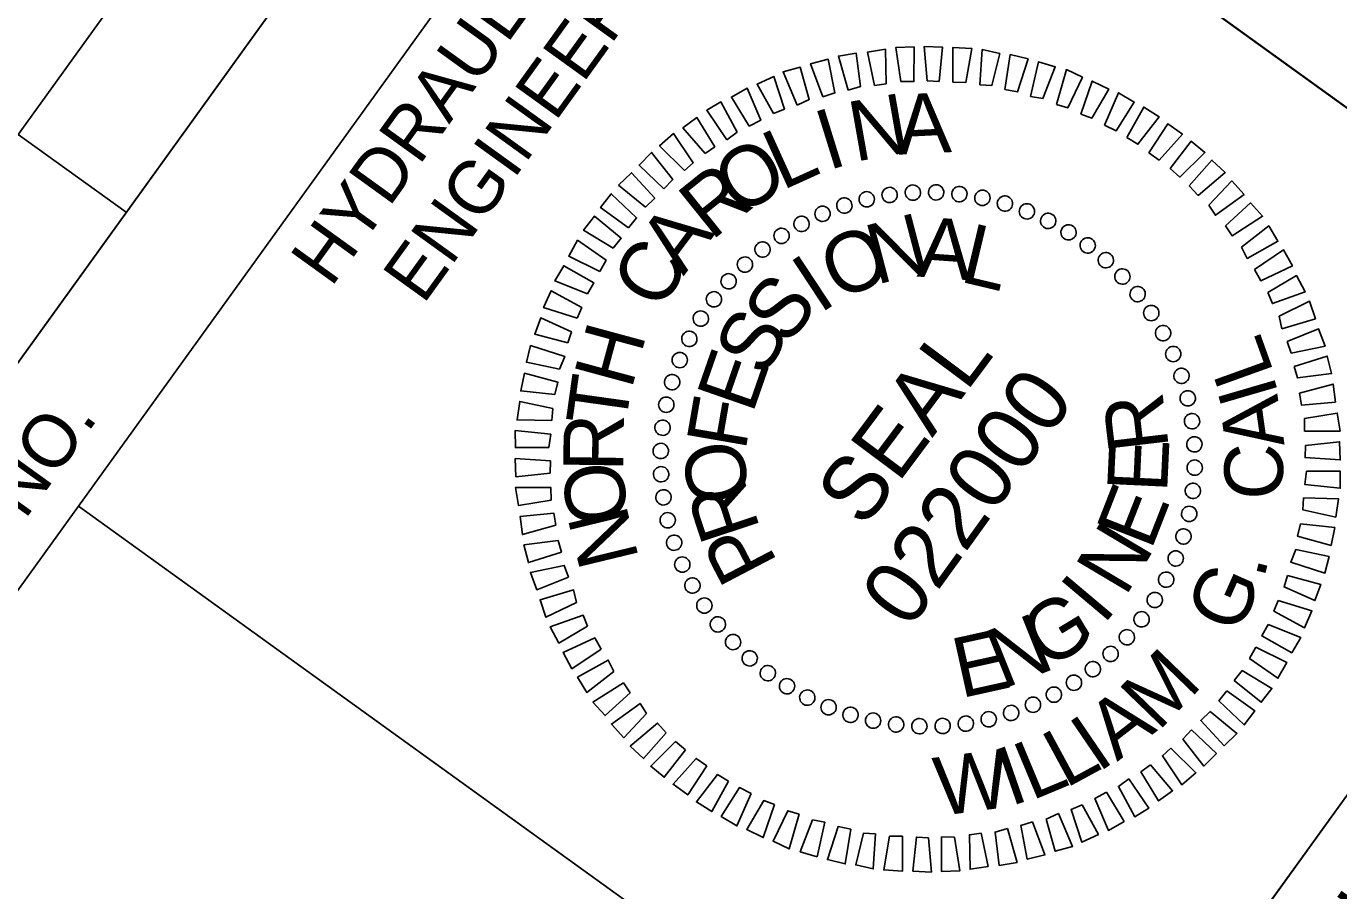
# Model space of a CAD drawing. Extents: x 2186840 to 2191350, y 386817 to 390793.
# Drawn here: x 2190437.4 to 2190560.6, y 388656.7 to 388737.9 of the extents above; entities that cross this region are included whole.
import ezdxf

# ---------------------------------------------------------------- set-up
doc = ezdxf.new("R2010")
doc.units = 0
for name, color, linetype in [('Sheet Plan CELL', 7, 'Continuous'), ('Sheet Plan Layout CELL', 7, 'Continuous'), ('Sheet Professional Seal CELL', 7, 'Continuous'), ('Sheet Sticker Exception Certification CELL', 7, 'Continuous')]:
    doc.layers.add(name, color=color, linetype=linetype)

msp = doc.modelspace()

# ---------------------------------------------------------------- linework, layer by layer
at = {"layer": 'Sheet Plan CELL'}
for p, q in [((2190363.46, 388626.27), (2190480.48, 388788.52)), ((2190373.63, 388618.95), (2190490.62, 388781.21)), ((2190373.63, 388618.95), (2190490.62, 388781.21)), ((2190426.47, 388734.97), (2190446.77, 388720.39)), ((2190442.28, 388692.79), (2190533.51, 388627.02))]:
    msp.add_line(p, q, dxfattribs=at)
for points in [[(2190470.32, 388795.89), (2189592.9, 387579.24), (2190444.54, 386965.06), (2191321.95, 388181.69)], [(2190353.28, 388633.62), (2190470.32, 388795.89), (2190490.62, 388781.21), (2190373.63, 388618.95)], [(2190442.28, 388692.79), (2190500.76, 388773.9), (2190592.02, 388708.09), (2190533.54, 388626.98)], [(2190444.54, 386965.06), (2189592.91, 387579.2), (2190353.28, 388633.62), (2190475, 388545.85), (2190592.02, 388708.09), (2191321.95, 388181.69)], [(2190383.76, 388611.64), (2190442.28, 388692.79), (2190533.54, 388626.98), (2190475, 388545.85)]]:
    msp.add_lwpolyline(points, close=True, dxfattribs=at)
at = {"layer": 'Sheet Plan Layout CELL'}
msp.add_lwpolyline([(2190501.89, 388478.1), (2190641.85, 388672.18), (2190470.33, 388795.9), (2190330.36, 388601.81)], close=True, dxfattribs=at)
at = {"layer": 'Sheet Professional Seal CELL'}
for p, q in [((2190516.31, 388721.65), (2190516.31, 388721.65)), ((2190518.44, 388722.03), (2190518.44, 388722.03)), ((2190520.65, 388722.28), (2190520.65, 388722.28)), ((2190522.8, 388722.27), (2190522.8, 388722.27)), ((2190525.02, 388722.1), (2190525.02, 388722.1)), ((2190527.18, 388721.77), (2190527.18, 388721.77)), ((2190514.19, 388721.02), (2190514.19, 388721.02)), ((2190529.27, 388721.25), (2190529.27, 388721.25)), ((2190531.33, 388720.5), (2190531.33, 388720.5)), ((2190510.18, 388719.3), (2190510.18, 388719.3)), ((2190512.13, 388720.29), (2190512.13, 388720.29)), ((2190533.34, 388719.54), (2190533.34, 388719.54)), ((2190508.28, 388718.2), (2190508.28, 388718.2)), ((2190535.26, 388718.53), (2190535.26, 388718.53)), ((2190506.48, 388716.91), (2190506.48, 388716.91)), ((2190537.08, 388717.28), (2190537.08, 388717.28)), ((2190504.89, 388715.47), (2190504.89, 388715.47)), ((2190538.77, 388715.87), (2190538.77, 388715.87)), ((2190540.31, 388714.33), (2190540.31, 388714.33)), ((2190503.34, 388713.93), (2190503.34, 388713.93)), ((2190501.94, 388712.23), (2190501.94, 388712.23)), ((2190541.75, 388712.74), (2190541.75, 388712.74)), ((2190543.05, 388710.94), (2190543.05, 388710.94)), ((2190500.69, 388710.42), (2190500.69, 388710.42)), ((2190499.68, 388708.5), (2190499.68, 388708.5)), ((2190544.14, 388709.04), (2190544.14, 388709.04)), ((2190545.14, 388707.09), (2190545.14, 388707.09)), ((2190498.71, 388706.48), (2190498.71, 388706.48)), ((2190497.97, 388704.43), (2190497.97, 388704.43)), ((2190545.87, 388705.02), (2190545.87, 388705.02)), ((2190497.45, 388702.34), (2190497.45, 388702.34)), ((2190546.5, 388702.9), (2190546.5, 388702.9)), ((2190546.88, 388700.78), (2190546.88, 388700.78)), ((2190497.12, 388700.17), (2190497.12, 388700.17)), ((2190547.13, 388698.57), (2190547.13, 388698.57)), ((2190496.94, 388697.96), (2190496.94, 388697.96)), ((2190522.03, 388697.19), (2190522.03, 388697.19)), ((2190496.93, 388695.81), (2190496.93, 388695.81)), ((2190547.12, 388696.41), (2190547.12, 388696.41)), ((2190497.18, 388693.59), (2190497.18, 388693.59)), ((2190546.94, 388694.2), (2190546.94, 388694.2)), ((2190546.61, 388692.03), (2190546.61, 388692.03)), ((2190497.56, 388691.47), (2190497.56, 388691.47)), ((2190546.09, 388689.94), (2190546.09, 388689.94)), ((2190498.19, 388689.35), (2190498.19, 388689.35)), ((2190498.92, 388687.28), (2190498.92, 388687.28)), ((2190545.35, 388687.89), (2190545.35, 388687.89)), ((2190544.39, 388685.87), (2190544.39, 388685.87)), ((2190499.92, 388685.33), (2190499.92, 388685.33)), ((2190501.01, 388683.43), (2190501.01, 388683.43)), ((2190543.37, 388683.95), (2190543.37, 388683.95)), ((2190502.31, 388681.63), (2190502.31, 388681.63)), ((2190542.13, 388682.14), (2190542.13, 388682.14)), ((2190503.75, 388680.04), (2190503.75, 388680.04)), ((2190540.72, 388680.44), (2190540.72, 388680.44)), ((2190505.29, 388678.5), (2190505.29, 388678.5)), ((2190539.18, 388678.9), (2190539.18, 388678.9)), ((2190537.58, 388677.46), (2190537.58, 388677.46)), ((2190506.98, 388677.09), (2190506.98, 388677.09)), ((2190535.79, 388676.17), (2190535.79, 388676.17)), ((2190508.8, 388675.84), (2190508.8, 388675.84)), ((2190510.72, 388674.83), (2190510.72, 388674.83)), ((2190533.89, 388675.07), (2190533.89, 388675.07)), ((2190512.74, 388673.87), (2190512.74, 388673.87)), ((2190531.93, 388674.08), (2190531.93, 388674.08)), ((2190514.79, 388673.13), (2190514.79, 388673.13)), ((2190516.88, 388672.6), (2190516.88, 388672.6)), ((2190525.63, 388672.34), (2190525.63, 388672.34)), ((2190527.75, 388672.72), (2190527.75, 388672.72)), ((2190529.87, 388673.35), (2190529.87, 388673.35)), ((2190519.05, 388672.28), (2190519.05, 388672.28)), ((2190521.26, 388672.1), (2190521.26, 388672.1)), ((2190523.41, 388672.09), (2190523.41, 388672.09))]:
    msp.add_line(p, q, dxfattribs=at)
for points in [[(2190514.55, 388731.86), (2190513.64, 388735.05), (2190515.32, 388735.32), (2190515.71, 388732.19)], [(2190517.02, 388732.3), (2190516.37, 388735.42), (2190518.05, 388735.69), (2190518.11, 388732.44)], [(2190519.51, 388732.66), (2190519.03, 388735.85), (2190520.74, 388735.91), (2190520.73, 388732.65)], [(2190521.97, 388732.74), (2190521.7, 388735.96), (2190523.43, 388735.88), (2190523.09, 388732.67)], [(2190524.39, 388732.6), (2190524.4, 388735.86), (2190526.17, 388735.75), (2190525.61, 388732.58)], [(2190526.93, 388732.36), (2190527.15, 388735.66), (2190528.79, 388735.28), (2190528.06, 388732.29)], [(2190529.26, 388731.92), (2190529.77, 388735.19), (2190531.45, 388734.78), (2190530.45, 388731.68)], [(2190509.77, 388730.44), (2190508.44, 388733.56), (2190510.05, 388734), (2190510.9, 388730.98)], [(2190512.18, 388731.23), (2190511.03, 388734.34), (2190512.69, 388734.75), (2190513.31, 388731.59)], [(2190531.69, 388731.27), (2190532.42, 388734.51), (2190534, 388734.05), (2190532.84, 388731.06)], [(2190507.53, 388729.65), (2190506.01, 388732.41), (2190507.58, 388733.13), (2190508.57, 388730.07)], [(2190534.11, 388730.52), (2190535.05, 388733.79), (2190536.56, 388733.06), (2190535.17, 388730.19)], [(2190536.41, 388729.6), (2190537.48, 388732.71), (2190539.03, 388731.96), (2190537.43, 388729.23)], [(2190505.25, 388728.46), (2190503.59, 388731.2), (2190505.07, 388732.04), (2190506.34, 388729.03)], [(2190538.62, 388728.56), (2190539.95, 388731.61), (2190541.42, 388730.73), (2190539.71, 388728.02)], [(2190503.17, 388727.19), (2190501.28, 388729.96), (2190502.59, 388730.75), (2190504.12, 388727.92)], [(2190540.74, 388727.4), (2190542.32, 388730.27), (2190543.75, 388729.36), (2190541.77, 388726.78)], [(2190501.12, 388725.89), (2190499.04, 388728.31), (2190500.36, 388729.28), (2190502.02, 388726.54)], [(2190542.8, 388725.98), (2190544.58, 388728.7), (2190545.95, 388727.71), (2190543.77, 388725.28)], [(2190499.19, 388724.32), (2190496.85, 388726.63), (2190498.16, 388727.77), (2190500.01, 388725.03)], [(2190544.79, 388724.48), (2190546.78, 388727.05), (2190548.06, 388726.01), (2190545.71, 388723.69)], [(2190497.25, 388722.58), (2190494.92, 388724.81), (2190496.09, 388726.01), (2190498.08, 388723.46)], [(2190495.52, 388720.86), (2190493, 388722.93), (2190494.21, 388724.09), (2190496.39, 388721.72)], [(2190546.59, 388722.87), (2190548.71, 388725.29), (2190549.97, 388724.13), (2190547.42, 388721.96)], [(2190548.43, 388721.05), (2190550.57, 388723.33), (2190551.74, 388722.06), (2190549.05, 388720.11)], [(2190493.94, 388718.92), (2190491.3, 388720.82), (2190492.31, 388722.13), (2190494.68, 388719.87)], [(2190550, 388719.12), (2190552.34, 388721.26), (2190553.47, 388720.01), (2190550.61, 388718.18)], [(2190492.49, 388717.01), (2190489.71, 388718.7), (2190490.72, 388720.01), (2190493.24, 388717.95)], [(2190551.5, 388717.11), (2190554.05, 388719.1), (2190554.92, 388717.66), (2190552.03, 388716.05)], [(2190491.24, 388714.83), (2190488.32, 388716.26), (2190489.15, 388717.75), (2190491.82, 388715.89)], [(2190552.7, 388715.01), (2190555.45, 388716.85), (2190556.27, 388715.34), (2190553.3, 388713.96)], [(2190490.07, 388712.71), (2190487.01, 388713.93), (2190487.85, 388715.36), (2190490.66, 388713.77)], [(2190553.98, 388712.86), (2190556.66, 388714.44), (2190557.48, 388712.92), (2190554.4, 388711.81)], [(2190489.12, 388710.44), (2190485.95, 388711.43), (2190486.66, 388713.02), (2190489.53, 388711.44)], [(2190555.03, 388710.62), (2190557.88, 388712.02), (2190558.43, 388710.39), (2190555.29, 388709.45)], [(2190488.24, 388708.12), (2190485.13, 388708.94), (2190485.68, 388710.46), (2190488.57, 388709.17)], [(2190555.77, 388708.24), (2190558.73, 388709.43), (2190559.35, 388707.82), (2190556.16, 388707.16)], [(2190487.46, 388705.66), (2190484.34, 388706.3), (2190484.73, 388707.87), (2190487.94, 388706.85)], [(2190556.43, 388705.91), (2190559.54, 388706.88), (2190559.95, 388705.23), (2190556.75, 388704.82)], [(2190487.02, 388703.26), (2190483.81, 388703.6), (2190484.15, 388705.27), (2190487.3, 388704.42)], [(2190556.95, 388703.38), (2190560.11, 388704.25), (2190560.31, 388702.56), (2190557.13, 388702.26)], [(2190486.74, 388700.82), (2190483.46, 388700.89), (2190483.72, 388702.62), (2190486.81, 388701.94)], [(2190557.41, 388701.02), (2190560.48, 388701.52), (2190560.75, 388699.84), (2190557.42, 388699.84)], [(2190486.46, 388698.3), (2190483.31, 388698.29), (2190483.3, 388699.9), (2190486.62, 388699.54)], [(2190557.49, 388698.49), (2190560.7, 388698.83), (2190560.76, 388697.12), (2190557.46, 388697.34)], [(2190486.57, 388695.88), (2190483.36, 388695.54), (2190483.3, 388697.25), (2190486.6, 388697.03)], [(2190557.6, 388696.07), (2190560.75, 388696.08), (2190560.76, 388694.47), (2190557.44, 388694.83)], [(2190486.66, 388693.35), (2190483.59, 388692.86), (2190483.31, 388694.53), (2190486.64, 388694.53)], [(2190557.32, 388693.56), (2190560.6, 388693.48), (2190560.34, 388691.75), (2190557.26, 388692.43)], [(2190487.11, 388690.99), (2190483.96, 388690.12), (2190483.75, 388691.81), (2190486.93, 388692.11)], [(2190557.04, 388691.11), (2190560.25, 388690.77), (2190559.91, 388689.1), (2190556.76, 388689.95)], [(2190487.63, 388688.46), (2190484.53, 388687.49), (2190484.11, 388689.14), (2190487.31, 388689.55)], [(2190556.61, 388688.71), (2190559.72, 388688.07), (2190559.33, 388686.5), (2190556.12, 388687.52)], [(2190488.29, 388686.13), (2190485.33, 388684.94), (2190484.71, 388686.56), (2190487.9, 388687.22)], [(2190555.82, 388686.26), (2190558.93, 388685.43), (2190558.39, 388683.91), (2190555.49, 388685.2)], [(2190489.04, 388683.75), (2190486.18, 388682.35), (2190485.63, 388683.98), (2190488.77, 388684.92)], [(2190554.94, 388683.93), (2190558.11, 388682.94), (2190557.4, 388681.35), (2190554.53, 388682.93)], [(2190490.08, 388681.52), (2190487.4, 388679.93), (2190486.58, 388681.45), (2190489.66, 388682.56)], [(2190553.99, 388681.66), (2190557.05, 388680.44), (2190556.21, 388679.01), (2190553.41, 388680.6)], [(2190491.36, 388679.36), (2190488.61, 388677.52), (2190487.79, 388679.03), (2190490.76, 388680.41)], [(2190552.83, 388679.54), (2190555.74, 388678.11), (2190554.91, 388676.62), (2190552.25, 388678.48)], [(2190492.56, 388677.26), (2190490.02, 388675.27), (2190489.14, 388676.71), (2190492.03, 388678.32)], [(2190551.57, 388677.36), (2190554.35, 388675.67), (2190553.34, 388674.36), (2190550.82, 388676.42)], [(2190494.07, 388675.25), (2190491.73, 388673.11), (2190490.59, 388674.36), (2190493.45, 388676.19)], [(2190550.12, 388675.45), (2190552.76, 388673.55), (2190551.75, 388672.24), (2190549.38, 388674.5)], [(2190495.63, 388673.32), (2190493.49, 388671.04), (2190492.32, 388672.32), (2190495.01, 388674.26)], [(2190497.47, 388671.5), (2190495.35, 388669.08), (2190494.09, 388670.24), (2190496.64, 388672.41)], [(2190548.54, 388673.51), (2190551.06, 388671.44), (2190549.85, 388670.28), (2190547.67, 388672.65)], [(2190546.81, 388671.79), (2190549.14, 388669.56), (2190547.97, 388668.37), (2190545.99, 388670.91)], [(2190499.27, 388669.89), (2190497.29, 388667.32), (2190496.01, 388668.36), (2190498.35, 388670.68)], [(2190544.87, 388670.05), (2190547.22, 388667.74), (2190545.9, 388666.6), (2190544.06, 388669.34)], [(2190501.27, 388668.39), (2190499.49, 388665.67), (2190498.11, 388666.66), (2190500.29, 388669.09)], [(2190503.32, 388666.97), (2190501.75, 388664.1), (2190500.31, 388665.01), (2190502.29, 388667.59)], [(2190542.94, 388668.48), (2190545.02, 388666.06), (2190543.7, 388665.1), (2190542.04, 388667.83)], [(2190505.44, 388665.81), (2190504.11, 388662.76), (2190502.64, 388663.64), (2190504.35, 388666.35)], [(2190540.9, 388667.18), (2190542.78, 388664.41), (2190541.47, 388663.62), (2190539.94, 388666.46)], [(2190507.65, 388664.77), (2190506.58, 388661.66), (2190505.03, 388662.41), (2190506.63, 388665.14)], [(2190538.81, 388665.91), (2190540.47, 388663.17), (2190539, 388662.33), (2190537.72, 388665.34)], [(2190509.95, 388663.85), (2190509.01, 388660.59), (2190507.5, 388661.31), (2190508.9, 388664.18)], [(2190534.3, 388663.93), (2190535.62, 388660.81), (2190534.01, 388660.37), (2190533.16, 388663.39)], [(2190536.53, 388664.72), (2190538.05, 388661.96), (2190536.49, 388661.24), (2190535.49, 388664.3)], [(2190512.37, 388663.1), (2190511.64, 388659.86), (2190510.06, 388660.33), (2190511.22, 388663.31)], [(2190514.8, 388662.45), (2190514.29, 388659.18), (2190512.61, 388659.59), (2190513.61, 388662.69)], [(2190529.51, 388662.51), (2190530.42, 388659.33), (2190528.75, 388659.05), (2190528.35, 388662.18)], [(2190531.88, 388663.14), (2190533.03, 388660.03), (2190531.38, 388659.62), (2190530.76, 388662.78)], [(2190517.13, 388662.01), (2190516.91, 388658.71), (2190515.27, 388659.09), (2190516.01, 388662.08)], [(2190519.67, 388661.78), (2190519.66, 388658.51), (2190517.89, 388658.62), (2190518.45, 388661.79)], [(2190522.1, 388661.63), (2190522.37, 388658.41), (2190520.63, 388658.49), (2190520.97, 388661.7)], [(2190524.55, 388661.71), (2190525.03, 388658.52), (2190523.33, 388658.46), (2190523.33, 388661.72)], [(2190527.04, 388662.07), (2190527.69, 388658.95), (2190526.01, 388658.68), (2190525.95, 388661.93)]]:
    msp.add_lwpolyline(points, close=True, dxfattribs=at)
for centre, major_axis in [((2190520.63, 388722.23), (-0.04, 0.719)), ((2190522.82, 388722.25), (0.023, 0.72)), ((2190525, 388722.09), (0.085, 0.715)), ((2190514.2, 388721.01), (-0.225, 0.684)), ((2190516.3, 388721.6), (-0.164, 0.701)), ((2190518.45, 388722.01), (-0.103, 0.713)), ((2190527.16, 388721.74), (0.147, 0.705)), ((2190529.28, 388721.2), (0.208, 0.689)), ((2190512.15, 388720.24), (-0.284, 0.662)), ((2190531.34, 388720.47), (0.267, 0.669)), ((2190533.34, 388719.57), (0.325, 0.643)), ((2190510.18, 388719.29), (-0.34, 0.635)), ((2190535.25, 388718.5), (0.379, 0.612)), ((2190508.3, 388718.17), (-0.394, 0.602)), ((2190537.05, 388717.27), (0.431, 0.577)), ((2190506.52, 388716.89), (-0.445, 0.566)), ((2190538.75, 388715.88), (0.48, 0.537)), ((2190504.86, 388715.47), (-0.493, 0.525)), ((2190503.33, 388713.9), (-0.537, 0.48)), ((2190540.31, 388714.35), (0.525, 0.493)), ((2190501.95, 388712.21), (-0.577, 0.431)), ((2190541.74, 388712.7), (0.566, 0.445)), ((2190500.72, 388710.4), (-0.612, 0.379)), ((2190543.02, 388710.92), (0.602, 0.394)), ((2190499.64, 388708.49), (-0.643, 0.325)), ((2190544.13, 388709.04), (0.635, 0.34)), ((2190498.74, 388706.5), (-0.669, 0.267)), ((2190545.08, 388707.07), (0.662, 0.284)), ((2190545.86, 388705.02), (0.684, 0.225)), ((2190498.02, 388704.43), (-0.689, 0.208)), ((2190546.45, 388702.91), (0.701, 0.164)), ((2190497.48, 388702.31), (-0.705, 0.147)), ((2190497.13, 388700.15), (-0.715, 0.085)), ((2190546.85, 388700.76), (0.713, 0.103)), ((2190496.96, 388697.97), (-0.72, 0.023)), ((2190547.07, 388698.59), (0.719, 0.04)), ((2190547.1, 388696.4), (0.72, -0.023)), ((2190496.99, 388695.78), (-0.719, -0.04)), ((2190546.93, 388694.22), (0.715, -0.085)), ((2190497.21, 388693.61), (-0.713, -0.103)), ((2190497.61, 388691.46), (-0.701, -0.164)), ((2190546.58, 388692.06), (0.705, -0.147)), ((2190498.21, 388689.35), (-0.684, -0.225)), ((2190546.04, 388689.94), (0.689, -0.208)), ((2190545.32, 388687.87), (0.669, -0.267)), ((2190498.98, 388687.3), (-0.662, -0.284)), ((2190499.93, 388685.33), (-0.635, -0.34)), ((2190544.42, 388685.88), (0.643, -0.325)), ((2190543.35, 388683.97), (0.612, -0.379)), ((2190501.05, 388683.45), (-0.602, -0.394)), ((2190502.32, 388681.68), (-0.566, -0.445)), ((2190542.11, 388682.16), (0.577, -0.431)), ((2190540.73, 388680.47), (0.537, -0.48)), ((2190503.75, 388680.02), (-0.525, -0.493)), ((2190505.31, 388678.49), (-0.48, -0.537)), ((2190539.2, 388678.9), (0.493, -0.525)), ((2190507.01, 388677.1), (-0.431, -0.577)), ((2190537.54, 388677.48), (0.445, -0.566)), ((2190508.82, 388675.87), (-0.379, -0.612)), ((2190535.76, 388676.2), (0.394, -0.602)), ((2190510.72, 388674.8), (-0.325, -0.643)), ((2190531.91, 388674.13), (0.284, -0.662)), ((2190533.88, 388675.08), (0.34, -0.635)), ((2190512.72, 388673.9), (-0.267, -0.669)), ((2190514.78, 388673.18), (-0.208, -0.689)), ((2190527.76, 388672.77), (0.164, -0.701)), ((2190529.86, 388673.36), (0.225, -0.684)), ((2190516.9, 388672.64), (-0.147, -0.705)), ((2190519.06, 388672.28), (-0.085, -0.715)), ((2190521.24, 388672.12), (-0.023, -0.72)), ((2190523.43, 388672.14), (0.04, -0.719)), ((2190525.61, 388672.36), (0.103, -0.713))]:
    msp.add_ellipse(centre, major_axis=major_axis, ratio=0.999708, dxfattribs=at)
at = {"layer": 'Sheet Sticker Exception Certification CELL'}
msp.add_line((2190475, 388545.85), (2190592.01, 388708.1), dxfattribs=at)
msp.add_line((2190475, 388545.85), (2190592.01, 388708.1), dxfattribs=at)

# ---------------------------------------------------------------- texts
at = {"layer": 'Sheet Plan CELL'}
for s, height, p in [('HYDRAULICS', 5, (2190466, 388713.24)), ('ENGINEER', 5, (2190474.66, 388711.64)), ('R/W SHEET NO.', 5.0001, (2190414.42, 388659.8))]:
    msp.add_text(s, height=height, rotation=54.2018, dxfattribs=at).set_placement(p)
at = {"layer": 'Sheet Professional Seal CELL'}
for s, height, rotation, p in [('N', 5.64, 10.0208, (2190515.18, 388725.12)), ('A', 5.64, 2.819, (2190519.3, 388725.79)), ('I', 5.64, 17.222, (2190512.66, 388724.29)), ('L', 5.64, 24.4227, (2190508.35, 388722.4)), ('O', 5.64, 31.623, (2190504.27, 388719.92)), ('R', 5.64, 38.8229, (2190501.7, 388717.64)), ('A', 5.64, 53.2222, (2190499.09, 388714.35)), ('N', 5.64, 14.6785, (2190517.19, 388713.56)), ('A', 5.64, 355.9621, (2190520.97, 388714.35)), ('L', 5.64, 346.6027, (2190524.91, 388713.91)), ('O', 5.64, 24.0353, (2190513.61, 388712.01)), ('C', 5.64, 60.4217, (2190497.02, 388710.97)), ('I', 5.64, 33.3914, (2190511.87, 388710.8)), ('S', 5.64, 52.1022, (2190508.79, 388707.72)), ('S', 5.64, 61.4575, (2190506.73, 388704.77)), ('H', 5.64, 74.8213, (2190494.2, 388703.64)), ('SEAL', 5.998, 53.2018, (2190516.04, 388690.59)), ('L', 5.5, 109.802, (2190554.57, 388705.31)), ('E', 5.64, 70.8129, (2190505.56, 388701.36)), ('T', 5.64, 82.0216, (2190493.63, 388700.03)), ('022000', 5.998, 54.2018, (2190520.29, 388681.08)), ('I', 5.5, 106.2815, (2190555, 388703.3)), ('R', 5.64, 96.6833, (2190544.68, 388698.24)), ('A', 5.5, 98.0957, (2190555.54, 388698.54)), ('F', 5.64, 80.1689, (2190504.9, 388697.89)), ('R', 5.64, 89.2223, (2190493.43, 388695.99)), ('O', 5.64, 98.8831, (2190505.37, 388693.48)), ('E', 5.64, 87.3259, (2190544.5, 388693.99)), ('C', 5.5, 89.223, (2190555.35, 388693.35)), ('O', 5.64, 96.4236, (2190493.92, 388691.38)), ('R', 5.64, 108.2415, (2190506.33, 388690.63)), ('E', 5.64, 68.6136, (2190542.99, 388688.55)), ('N', 5.64, 103.6253, (2190494.93, 388687.82)), ('N', 5.64, 59.2582, (2190540.58, 388684.18)), ('P', 5.64, 117.6007, (2190507.99, 388687.46)), ('.', 5.5, 76.0427, (2190553.59, 388685.86)), ('I', 5.64, 49.903, (2190538.5, 388681.55)), ('G', 5.5, 66.111, (2190551.17, 388680.58)), ('G', 5.64, 31.1921, (2190533.12, 388677.35)), ('N', 5.64, 21.8358, (2190529.08, 388675.58)), ('E', 5.64, 12.4787, (2190525.13, 388674.73)), ('M', 5.5, 45.99, (2190543.68, 388671.57)), ('A', 5.5, 37.8042, (2190539.81, 388668.75)), ('I', 5.5, 34.2837, (2190538.03, 388667.71)), ('L', 5.5, 28.4735, (2190534.97, 388666.25)), ('W', 5.5, 7.5368, (2190523.06, 388663.67)), ('I', 5.5, 19.1429, (2190529.78, 388664.56)), ('L', 5.5, 22.6633, (2190531.77, 388665.1))]:
    msp.add_text(s, height=height, rotation=rotation, dxfattribs=at).set_placement(p)
at = {"layer": 'Sheet Sticker Exception Certification CELL'}
for s, p in [('DOCUMENT NOT CONSIDERED FINAL', (2190495.72, 388556.89)), ('DOCUMENT NOT CONSIDERED FINAL', (2190495.72, 388556.89)), ('UNLESS ALL SIGNATURES COMPLETED', (2190499.89, 388547.63)), ('UNLESS ALL SIGNATURES COMPLETED', (2190499.89, 388547.63))]:
    msp.add_text(s, height=5.5, rotation=54.2018, dxfattribs=at).set_placement(p)

doc.saveas('drawing.dxf')
